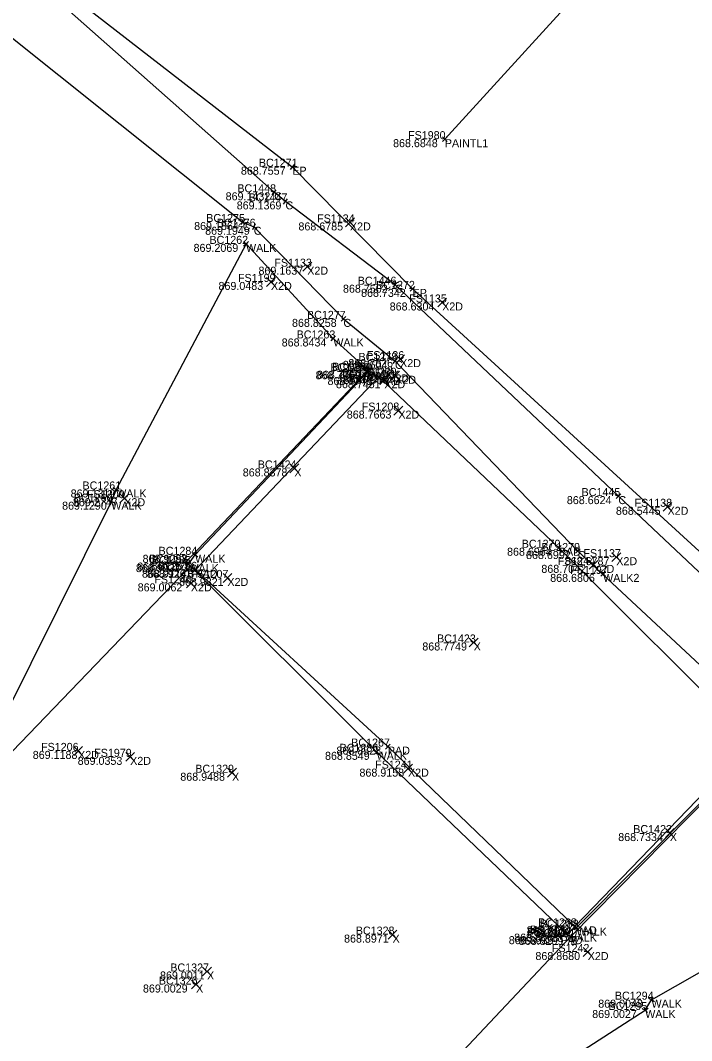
# Model space of a CAD drawing. Extents: x 1479425 to 1480294, y 379351 to 380102.
# Drawn here: x 1479653.49 to 1479658.52, y 379862.2 to 379869.84 of the extents above; entities that cross this region are included whole.
import ezdxf

# ---------------------------------------------------------------- set-up
doc = ezdxf.new("R2010")
doc.units = 0
for name, color, linetype in [('PM_X_Crosswalk', 7, 'Continuous'), ('PV_X_Curb', 7, 'Continuous'), ('PV_X_Walk', 7, 'Continuous'), ('RD_X_Concrete_Pad', 7, 'Continuous'), ('SV_X_Break_Lines', 7, 'Continuous'), ('SV_X_Random_Point', 7, 'Continuous'), ('SV_X_Shot_Marker', 7, 'Continuous'), ('SV_X_Text_Comment', 7, 'Continuous'), ('SV_X_Text_Elevation', 7, 'Continuous'), ('SV_X_Text_Name', 7, 'Continuous')]:
    doc.layers.add(name, color=color, linetype=linetype)

msp = doc.modelspace()

# ---------------------------------------------------------------- linework, layer by layer
at = {"layer": 'PM_X_Crosswalk'}
msp.add_lwpolyline([(1479656.672, 379868.9513), (1479694.216, 379910.0838)], dxfattribs=at)
at = {"layer": 'PV_X_Curb'}
for points in [[(1479674.4002, 379850.8088), (1479663.165, 379861.2618), (1479660.4814, 379863.897), (1479660.3417, 379864.0048), (1479659.4756, 379864.8615), (1479657.9728, 379866.276), (1479656.299, 379867.8605), (1479655.4781, 379868.4849), (1479655.3936, 379868.553), (1479653.3405, 379870.3718), (1479649.8028, 379873.0366), (1479644.8359, 379875.8815), (1479640.9714, 379876.9839), (1479637.7316, 379877.6879), (1479634.8886, 379878.0569), (1479629.5507, 379877.9769), (1479626.9417, 379877.5496), (1479624.927, 379877.2311), (1479623.2196, 379876.8713), (1479619.5522, 379875.9957), (1479615.007, 379874.7968)], [(1479644.7184, 379876.0341), (1479650.0207, 379873.0081), (1479655.5289, 379868.7448), (1479656.4303, 379867.8292), (1479659.4657, 379865.0505), (1479660.571, 379864.0064), (1479667.529, 379857.5214), (1479674.5498, 379850.8162), (1479681.356, 379844.5574), (1479695.384, 379831.4158), (1479709.512, 379818.1305), (1479724.003, 379804.7278), (1479730.662, 379798.2721), (1479750.68, 379779.6901), (1479759.253, 379771.8932), (1479760.555, 379770.78), (1479775.03, 379758.526), (1479788.183, 379747.5851), (1479800.537, 379737.2509), (1479801.677, 379736.2915)], [(1479644.5411, 379875.6244), (1479649.735, 379872.6614), (1479655.1572, 379868.3304), (1479655.2406, 379868.2948), (1479655.9122, 379867.6044), (1479656.2985, 379867.2898), (1479657.669, 379865.8645), (1479659.1303, 379864.4974), (1479660.094, 379863.6509), (1479660.2213, 379863.6582), (1479667.239, 379857.1215), (1479681.024, 379844.2076), (1479695.135, 379830.9784), (1479709.331, 379817.7082), (1479723.729, 379804.1927), (1479729.719, 379798.6), (1479748.963, 379780.548), (1479759.065, 379771.4845), (1479760.185, 379770.4729), (1479774.837, 379758.1297), (1479787.835, 379747.1604), (1479799.962, 379737.1088), (1479801.3, 379736.0452)]]:
    msp.add_lwpolyline(points, dxfattribs=at)
at = {"layer": 'PV_X_Walk'}
msp.add_lwpolyline([(1479656.4412, 379861.3061), (1479658.1736, 379862.4244), (1479658.2208, 379862.5019), (1479660.0376, 379863.5356), (1479659.0442, 379864.4378), (1479657.6587, 379863.0418), (1479657.5845, 379862.997), (1479656.1611, 379864.3595), (1479654.7505, 379865.7665), (1479654.8005, 379865.8361), (1479656.1025, 379867.2161), (1479655.8364, 379867.4576), (1479655.1823, 379868.1665), (1479654.209, 379866.3257), (1479654.1723, 379866.2342), (1479653.1639, 379864.2126), (1479653.1023, 379864.143), (1479653.0159, 379864.2566), (1479651.5463, 379865.5811), (1479650.1586, 379866.8771), (1479650.1004, 379866.9858), (1479648.689, 379868.2743), (1479647.1434, 379869.696)], dxfattribs=at)
at = {"layer": 'RD_X_Concrete_Pad'}
msp.add_lwpolyline([(1479656.1774, 379867.1692), (1479654.8041, 379865.7236), (1479656.2454, 379864.3988), (1479657.6462, 379863.0515), (1479658.9828, 379864.4335), (1479657.5266, 379865.8891)], close=True, dxfattribs=at)
at = {"layer": 'SV_X_Break_Lines'}
for points in [[(1479653.2434, 379864.1704), (1479654.7413, 379865.7248), (1479654.7294, 379865.7779), (1479656.0888, 379867.2117)], [(1479659.0338, 379864.4109), (1479657.6127, 379862.9726), (1479656.567, 379861.8603)]]:
    msp.add_lwpolyline(points, dxfattribs=at)
at = {"layer": 'SV_X_Random_Point'}
for p, q in [((1479655.9277, 379868.2939), (1479655.9943, 379868.3607)), ((1479655.9277, 379868.3607), (1479655.9943, 379868.2939)), ((1479655.6077, 379867.9621), (1479655.6743, 379868.0289)), ((1479655.6077, 379868.0289), (1479655.6743, 379867.9621)), ((1479655.3357, 379867.8479), (1479655.4023, 379867.9147)), ((1479655.3357, 379867.9147), (1479655.4023, 379867.8479)), ((1479656.6187, 379867.6939), (1479656.6853, 379867.7607)), ((1479656.6187, 379867.7607), (1479656.6853, 379867.6939)), ((1479656.3037, 379867.2691), (1479656.3703, 379867.3359)), ((1479656.3037, 379867.3359), (1479656.3703, 379867.2691)), ((1479656.1857, 379867.1114), (1479656.2523, 379867.1782)), ((1479656.1857, 379867.1782), (1479656.2523, 379867.1114)), ((1479656.2147, 379867.1543), (1479656.2813, 379867.2211)), ((1479656.2147, 379867.2211), (1479656.2813, 379867.1543)), ((1479656.2667, 379867.1451), (1479656.3333, 379867.2119)), ((1479656.2667, 379867.2119), (1479656.3333, 379867.1451)), ((1479656.2907, 379866.8837), (1479656.3573, 379866.9505)), ((1479656.2907, 379866.9505), (1479656.3573, 379866.8837)), ((1479655.5109, 379866.4501), (1479655.5775, 379866.5169)), ((1479655.5109, 379866.5169), (1479655.5775, 379866.4501)), ((1479654.2367, 379866.2268), (1479654.3033, 379866.2936)), ((1479654.2367, 379866.2936), (1479654.3033, 379866.2268)), ((1479658.3077, 379866.1625), (1479658.3743, 379866.2293)), ((1479658.3077, 379866.2293), (1479658.3743, 379866.1625)), ((1479657.9237, 379865.785), (1479657.9903, 379865.8518)), ((1479657.9237, 379865.8518), (1479657.9903, 379865.785)), ((1479657.7527, 379865.7275), (1479657.8193, 379865.7943)), ((1479657.7527, 379865.7943), (1479657.8193, 379865.7275)), ((1479655.0097, 379865.6295), (1479655.0763, 379865.6963)), ((1479655.0097, 379865.6963), (1479655.0763, 379865.6295)), ((1479654.7357, 379865.5888), (1479654.8023, 379865.6556)), ((1479654.7357, 379865.6556), (1479654.8023, 379865.5888)), ((1479656.855, 379865.1456), (1479656.9216, 379865.2124)), ((1479656.855, 379865.2124), (1479656.9216, 379865.1456)), ((1479653.8907, 379864.333), (1479653.9573, 379864.3998)), ((1479653.8907, 379864.3998), (1479653.9573, 379864.333)), ((1479654.2807, 379864.2885), (1479654.3473, 379864.3553)), ((1479654.2807, 379864.3553), (1479654.3473, 379864.2885)), ((1479656.3627, 379864.2002), (1479656.4293, 379864.267)), ((1479656.3627, 379864.267), (1479656.4293, 379864.2002)), ((1479655.0443, 379864.1693), (1479655.1109, 379864.2361)), ((1479655.0443, 379864.2361), (1479655.1109, 379864.1693)), ((1479658.3246, 379863.7172), (1479658.3912, 379863.784)), ((1479658.3246, 379863.784), (1479658.3912, 379863.7172)), ((1479656.2469, 379862.9562), (1479656.3135, 379863.023)), ((1479656.2469, 379863.023), (1479656.3135, 379862.9562)), ((1479657.7097, 379862.8255), (1479657.7763, 379862.8923)), ((1479657.7097, 379862.8923), (1479657.7763, 379862.8255)), ((1479654.8564, 379862.6797), (1479654.923, 379862.7465)), ((1479654.8564, 379862.7465), (1479654.923, 379862.6797)), ((1479654.7743, 379862.582), (1479654.8409, 379862.6488)), ((1479654.7743, 379862.6488), (1479654.8409, 379862.582))]:
    msp.add_line(p, q, dxfattribs=at)
at = {"layer": 'SV_X_Shot_Marker'}
for p, q in [((1479656.6535, 379868.9682), (1479656.6905, 379868.9345)), ((1479656.6551, 379868.9329), (1479656.6889, 379868.9698)), ((1479656.672, 379868.9513), (1479656.672, 379868.9513)), ((1479655.5091, 379868.7601), (1479655.5487, 379868.7295)), ((1479655.5442, 379868.7646), (1479655.5136, 379868.725)), ((1479655.5289, 379868.7448), (1479655.5289, 379868.7448)), ((1479655.4131, 379868.5373), (1479655.3741, 379868.5687)), ((1479655.3779, 379868.5336), (1479655.4093, 379868.5725)), ((1479655.3936, 379868.553), (1479655.3936, 379868.553)), ((1479655.498, 379868.4698), (1479655.4582, 379868.5001)), ((1479655.463, 379868.465), (1479655.4932, 379868.5048)), ((1479655.4781, 379868.4849), (1479655.4781, 379868.4849)), ((1479655.1377, 379868.346), (1479655.1767, 379868.3148)), ((1479655.1728, 379868.35), (1479655.1416, 379868.3109)), ((1479655.1572, 379868.3304), (1479655.1572, 379868.3304)), ((1479655.2176, 379868.3046), (1479655.2636, 379868.285)), ((1479655.2504, 379868.3178), (1479655.2308, 379868.2718)), ((1479655.2406, 379868.2948), (1479655.2406, 379868.2948)), ((1479655.1639, 379868.1496), (1479655.2007, 379868.1835)), ((1479655.1992, 379868.1481), (1479655.1653, 379868.1849)), ((1479655.1823, 379868.1665), (1479655.1823, 379868.1665)), ((1479656.3172, 379867.8433), (1479656.2808, 379867.8777)), ((1479656.2818, 379867.8424), (1479656.3162, 379867.8787)), ((1479656.299, 379867.8605), (1479656.299, 379867.8605)), ((1479656.4481, 379867.8468), (1479656.4125, 379867.8117)), ((1479656.4128, 379867.847), (1479656.4478, 379867.8114)), ((1479656.4303, 379867.8292), (1479656.4303, 379867.8292)), ((1479655.9301, 379867.6219), (1479655.8943, 379867.587)), ((1479655.8948, 379867.6223), (1479655.9296, 379867.5865)), ((1479655.9122, 379867.6044), (1479655.9122, 379867.6044)), ((1479655.8549, 379867.4408), (1479655.8179, 379867.4744)), ((1479655.8196, 379867.4391), (1479655.8532, 379867.4761)), ((1479655.8364, 379867.4576), (1479655.8364, 379867.4576)), ((1479656.2791, 379867.3056), (1479656.3179, 379867.274)), ((1479656.3143, 379867.3092), (1479656.2827, 379867.2704)), ((1479656.0707, 379867.2289), (1479656.107, 379867.1945)), ((1479656.0716, 379867.1935), (1479656.106, 379867.2298)), ((1479656.0843, 379867.2333), (1479656.1207, 379867.199)), ((1479656.0853, 379867.1979), (1479656.1197, 379867.2343)), ((1479656.2985, 379867.2898), (1479656.2985, 379867.2898)), ((1479656.0888, 379867.2117), (1479656.0888, 379867.2117)), ((1479656.1025, 379867.2161), (1479656.1025, 379867.2161)), ((1479656.1955, 379867.152), (1479656.1593, 379867.1864)), ((1479656.1946, 379867.1873), (1479656.1602, 379867.1511)), ((1479656.1774, 379867.1692), (1479656.1774, 379867.1692)), ((1479654.2311, 379866.314), (1479654.1869, 379866.3374)), ((1479654.2207, 379866.3478), (1479654.1973, 379866.3036)), ((1479654.209, 379866.3257), (1479654.209, 379866.3257)), ((1479654.1955, 379866.2249), (1479654.1491, 379866.2435)), ((1479654.1816, 379866.2574), (1479654.163, 379866.211)), ((1479654.1723, 379866.2342), (1479654.1723, 379866.2342)), ((1479657.991, 379866.2589), (1479657.9546, 379866.2932)), ((1479657.9557, 379866.2578), (1479657.9899, 379866.2942)), ((1479657.9728, 379866.276), (1479657.9728, 379866.276)), ((1479654.7802, 379865.8507), (1479654.8208, 379865.8215)), ((1479654.7859, 379865.8158), (1479654.8151, 379865.8564)), ((1479657.5089, 379865.8714), (1479657.5443, 379865.9068)), ((1479657.5443, 379865.8714), (1479657.5089, 379865.9068)), ((1479657.5266, 379865.8891), (1479657.5266, 379865.8891)), ((1479657.687, 379865.8818), (1479657.651, 379865.8472)), ((1479657.6517, 379865.8825), (1479657.6863, 379865.8465)), ((1479657.669, 379865.8645), (1479657.669, 379865.8645)), ((1479654.705, 379865.7724), (1479654.7538, 379865.7833)), ((1479654.7349, 379865.7535), (1479654.7239, 379865.8022)), ((1479654.7294, 379865.7779), (1479654.7294, 379865.7779)), ((1479654.7328, 379865.7488), (1479654.7682, 379865.7842)), ((1479654.7682, 379865.7489), (1479654.7328, 379865.7842)), ((1479654.8005, 379865.8361), (1479654.8005, 379865.8361)), ((1479654.7233, 379865.7422), (1479654.7593, 379865.7075)), ((1479654.7239, 379865.7068), (1479654.7586, 379865.7428)), ((1479654.7413, 379865.7248), (1479654.7413, 379865.7248)), ((1479654.7505, 379865.7665), (1479654.7505, 379865.7665)), ((1479654.8222, 379865.7064), (1479654.786, 379865.7408)), ((1479654.8213, 379865.7417), (1479654.7869, 379865.7055)), ((1479654.8041, 379865.7236), (1479654.8041, 379865.7236)), ((1479657.8399, 379865.6759), (1479657.8761, 379865.7104)), ((1479657.8753, 379865.675), (1479657.8407, 379865.7112)), ((1479657.858, 379865.6931), (1479657.858, 379865.6931)), ((1479656.227, 379864.4157), (1479656.2638, 379864.3819)), ((1479656.2623, 379864.4172), (1479656.2285, 379864.3804)), ((1479656.2454, 379864.3988), (1479656.2454, 379864.3988)), ((1479656.1792, 379864.3422), (1479656.143, 379864.3768)), ((1479656.1438, 379864.3415), (1479656.1784, 379864.3776)), ((1479656.1611, 379864.3595), (1479656.1611, 379864.3595)), ((1479657.5974, 379862.9756), (1479657.5716, 379863.0184)), ((1479657.6282, 379863.0688), (1479657.6642, 379863.0342)), ((1479657.6635, 379863.0695), (1479657.6289, 379863.0335)), ((1479657.6765, 379863.0242), (1479657.641, 379863.0594)), ((1479657.6763, 379863.0596), (1479657.6411, 379863.0241)), ((1479657.6462, 379863.0515), (1479657.6462, 379863.0515)), ((1479657.6587, 379863.0418), (1479657.6587, 379863.0418)), ((1479657.514, 379862.9778), (1479657.564, 379862.9778)), ((1479657.539, 379863.0028), (1479657.539, 379862.9528)), ((1479657.539, 379862.9778), (1479657.539, 379862.9778)), ((1479657.6059, 379863.0099), (1479657.5631, 379862.9841)), ((1479657.5845, 379862.997), (1479657.5845, 379862.997)), ((1479657.6305, 379862.955), (1479657.5949, 379862.9902)), ((1479657.6303, 379862.9904), (1479657.5951, 379862.9548)), ((1479657.6127, 379862.9726), (1479657.6127, 379862.9726)), ((1479658.1994, 379862.5149), (1479658.2421, 379862.4889)), ((1479658.2078, 379862.4806), (1479658.2338, 379862.5233)), ((1479658.2208, 379862.5019), (1479658.2208, 379862.5019)), ((1479658.1526, 379862.4109), (1479658.1946, 379862.438)), ((1479658.16, 379862.4454), (1479658.1872, 379862.4034)), ((1479658.1736, 379862.4244), (1479658.1736, 379862.4244))]:
    msp.add_line(p, q, dxfattribs=at)

# ---------------------------------------------------------------- texts
at = {"layer": 'SV_X_Text_Comment'}
for s, p in [('PAINTL1', (1479656.672, 379868.8913)), ('EP', (1479655.5289, 379868.6848)), ('C', (1479655.3936, 379868.493)), ('C', (1479655.4781, 379868.4249)), ('C', (1479655.1572, 379868.2704)), ('C', (1479655.2406, 379868.2348)), ('X2D', (1479655.961, 379868.2673)), ('WALK', (1479655.1823, 379868.1065)), ('X2D', (1479655.641, 379867.9355)), ('X2D', (1479655.369, 379867.8213)), ('C', (1479656.299, 379867.8005)), ('EP', (1479656.4303, 379867.7692)), ('X2D', (1479656.652, 379867.6673)), ('C', (1479655.9122, 379867.5444)), ('WALK', (1479655.8364, 379867.3976)), ('X2D', (1479656.337, 379867.2425)), ('C', (1479656.2985, 379867.2298)), ('B', (1479656.0888, 379867.1517)), ('WALK', (1479656.1025, 379867.1561)), ('PAD', (1479656.1774, 379867.1092)), ('X2D', (1479656.248, 379867.1277)), ('X2D', (1479656.3, 379867.1185)), ('X2D', (1479656.219, 379867.0848)), ('X2D', (1479656.324, 379866.8571)), ('X', (1479655.5442, 379866.4235)), ('WALK', (1479654.209, 379866.2657)), ('WALK', (1479654.1723, 379866.1742)), ('X2D', (1479654.27, 379866.2002)), ('C', (1479657.9728, 379866.216)), ('X2D', (1479658.341, 379866.1359)), ('PAD', (1479657.5266, 379865.8291)), ('C', (1479657.669, 379865.8045)), ('B', (1479654.7294, 379865.7179)), ('WALK', (1479654.8005, 379865.7761)), ('X2D', (1479657.957, 379865.7584)), ('B', (1479654.7413, 379865.6648)), ('WALK', (1479654.7505, 379865.7065)), ('PAD', (1479654.8041, 379865.6636)), ('X2D', (1479657.786, 379865.7009)), ('WALK2', (1479657.858, 379865.6331)), ('X2D', (1479654.769, 379865.5622)), ('X2D', (1479655.043, 379865.6029)), ('X', (1479656.8883, 379865.119)), ('PAD', (1479656.2454, 379864.3388)), ('X2D', (1479653.924, 379864.3064)), ('X2D', (1479654.314, 379864.2619)), ('WALK', (1479656.1611, 379864.2995)), ('X', (1479655.0776, 379864.1427)), ('X2D', (1479656.396, 379864.1736)), ('X', (1479658.3579, 379863.6906)), ('PAD', (1479657.6462, 379862.9915)), ('WALK', (1479657.6587, 379862.9818)), ('X', (1479656.2802, 379862.9296)), ('PAD', (1479657.539, 379862.9178)), ('WALK', (1479657.5845, 379862.937)), ('B', (1479657.6127, 379862.9126)), ('X2D', (1479657.743, 379862.7989)), ('X', (1479654.8897, 379862.6531)), ('X', (1479654.8076, 379862.5554)), ('WALK', (1479658.2208, 379862.4419)), ('WALK', (1479658.1736, 379862.3644))]:
    msp.add_text(s, height=0.06, dxfattribs=at).set_placement(p)
at = {"layer": 'SV_X_Text_Elevation'}
for s, p in [('868.6848', (1479656.2841, 379868.8913)), ('868.7557', (1479655.1439, 379868.6848)), ('869.1432', (1479655.0294, 379868.493)), ('869.1369', (1479655.1125, 379868.4249)), ('869.1864', (1479654.7935, 379868.2704)), ('869.1949', (1479654.8755, 379868.2348)), ('868.6785', (1479655.575, 379868.2673)), ('869.2069', (1479654.7892, 379868.1065)), ('869.1637', (1479655.2759, 379867.9355)), ('869.0483', (1479654.976, 379867.8213)), ('868.7502', (1479655.9088, 379867.8005)), ('868.7342', (1479656.0443, 379867.7692)), ('868.6304', (1479656.2589, 379867.6673)), ('868.8258', (1479655.5267, 379867.5444)), ('868.8434', (1479655.4495, 379867.3976)), ('868.7826', (1479655.9491, 379867.2425)), ('868.7604', (1479655.9073, 379867.2298)), ('868.7769', (1479655.7034, 379867.1517)), ('868.7750', (1479655.7132, 379867.1561)), ('868.7745', (1479655.7929, 379867.1092)), ('868.7219', (1479655.8871, 379867.1277)), ('868.7359', (1479655.9136, 379867.1185)), ('868.7451', (1479655.8561, 379867.0848)), ('868.7663', (1479655.9371, 379866.8571)), ('868.8378', (1479655.1578, 379866.4235)), ('869.1319', (1479653.868, 379866.2657)), ('869.1290', (1479653.8038, 379866.1742)), ('869.2747', (1479653.8845, 379866.2002)), ('868.6624', (1479657.5864, 379866.216)), ('868.5445', (1479657.9541, 379866.1359)), ('868.6964', (1479657.1383, 379865.8291)), ('868.6992', (1479657.2807, 379865.8045)), ('868.9215', (1479654.3671, 379865.7179)), ('868.9097', (1479654.407, 379865.7761)), ('868.6787', (1479657.571, 379865.7584)), ('868.9037', (1479654.357, 379865.7065)), ('868.9114', (1479654.4022, 379865.6648)), ('868.9261', (1479654.4398, 379865.6636)), ('868.7042', (1479657.3953, 379865.7009)), ('868.6806', (1479657.4616, 379865.6331)), ('869.0062', (1479654.3703, 379865.5622)), ('868.9821', (1479654.6796, 379865.6029)), ('868.7749', (1479656.5033, 379865.119)), ('868.8528', (1479655.8599, 379864.3388)), ('869.1188', (1479653.5839, 379864.3064)), ('869.0353', (1479653.9205, 379864.2619)), ('868.8549', (1479655.7742, 379864.2995)), ('868.9488', (1479654.6897, 379864.1427)), ('868.9158', (1479656.0323, 379864.1736)), ('868.7334', (1479657.9715, 379863.6906)), ('868.8124', (1479657.2853, 379862.9915)), ('868.8012', (1479657.2912, 379862.9818)), ('868.8971', (1479655.9168, 379862.9296)), ('868.8635', (1479657.1511, 379862.9178)), ('868.8068', (1479657.1914, 379862.937)), ('868.8299', (1479657.2263, 379862.9126)), ('868.8680', (1479657.3509, 379862.7989)), ('869.0011', (1479654.5377, 379862.6531)), ('869.0029', (1479654.4098, 379862.5554)), ('869.0048', (1479657.8216, 379862.4419)), ('869.0027', (1479657.7763, 379862.3644))]:
    msp.add_text(s, height=0.06, dxfattribs=at).set_placement(p)
at = {"layer": 'SV_X_Text_Name'}
for s, p in [('FS1980', (1479656.3966, 379868.9513)), ('BC1271', (1479655.2784, 379868.7448)), ('BC1448', (1479655.1173, 379868.553)), ('BC1447', (1479655.2023, 379868.4849)), ('BC1275', (1479654.8842, 379868.3304)), ('FS1134', (1479655.7149, 379868.3273)), ('BC1276', (1479654.9638, 379868.2948)), ('BC1262', (1479654.9079, 379868.1665)), ('FS1133', (1479655.3945, 379867.9955)), ('FS1199', (1479655.122, 379867.8813)), ('BC1446', (1479656.0194, 379867.8605)), ('BC1272', (1479656.1577, 379867.8292)), ('FS1135', (1479656.4055, 379867.7273)), ('BC1277', (1479655.6392, 379867.6044)), ('BC1263', (1479655.5615, 379867.4576)), ('BC1278', (1479656.025, 379867.2898)), ('FS1136', (1479656.0867, 379867.3025)), ('BC1259', (1479655.8144, 379867.2117)), ('BC1264', (1479655.8281, 379867.2161)), ('BC1265', (1479655.9025, 379867.1692)), ('FS1198', (1479656.001, 379867.1877)), ('FS1239', (1479656.0303, 379867.1785)), ('FS1245', (1479655.9502, 379867.1448)), ('FS1208', (1479656.0496, 379866.9171)), ('BC1424', (1479655.2702, 379866.4835)), ('BC1261', (1479653.9566, 379866.3257)), ('FS1200', (1479653.9908, 379866.2602)), ('BC1445', (1479657.697, 379866.276)), ('BC1260', (1479653.8922, 379866.2342)), ('FS1138', (1479658.094, 379866.1959)), ('BC1270', (1479657.2484, 379865.8891)), ('BC1279', (1479657.3955, 379865.8645)), ('BC1284', (1479654.527, 379865.8361)), ('FS1137', (1479657.7105, 379865.8184)), ('BC1258', (1479654.455, 379865.7779)), ('BC1257', (1479654.4673, 379865.7248)), ('BC1285', (1479654.4765, 379865.7665)), ('BC1266', (1479654.5254, 379865.7236)), ('FS1244', (1479657.5177, 379865.7609)), ('FS1207', (1479654.769, 379865.6629)), ('FS1197', (1479657.6115, 379865.6931)), ('FS1240', (1479654.495, 379865.6222)), ('BC1423', (1479656.6139, 379865.179)), ('FS1206', (1479653.6463, 379864.3664)), ('BC1286', (1479655.8834, 379864.3595)), ('BC1267', (1479655.9705, 379864.3988)), ('FS1979', (1479654.0443, 379864.3219)), ('BC1329', (1479654.8022, 379864.2027)), ('FS1241', (1479656.1498, 379864.2336)), ('BC1422', (1479658.0839, 379863.7506)), ('BC1268', (1479657.3708, 379863.0515)), ('BC1288', (1479657.3843, 379863.0418)), ('BC1328', (1479656.0048, 379862.9896)), ('FS1210', (1479657.2892, 379862.9778)), ('BC1287', (1479657.3105, 379862.997)), ('BC1291', (1479657.3603, 379862.9726)), ('FS1242', (1479657.4747, 379862.8589)), ('BC1327', (1479654.6148, 379862.7131)), ('BC1326', (1479654.5289, 379862.6154)), ('BC1294', (1479657.9464, 379862.5019)), ('BC1295', (1479657.8987, 379862.4244))]:
    msp.add_text(s, height=0.06, dxfattribs=at).set_placement(p)

doc.saveas('drawing.dxf')
